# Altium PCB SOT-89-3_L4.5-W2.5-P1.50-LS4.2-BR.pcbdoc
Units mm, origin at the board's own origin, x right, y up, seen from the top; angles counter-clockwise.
Board outline 18.08 x 17.35 mm, 2 copper layers (Top Layer, Bottom Layer), stack 0.07 mm thick; 1 components, 0 nets, 3 pads, 0 vias.
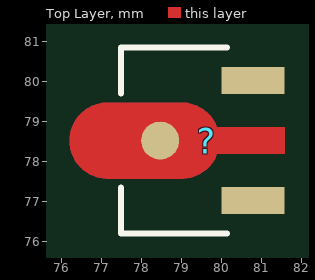
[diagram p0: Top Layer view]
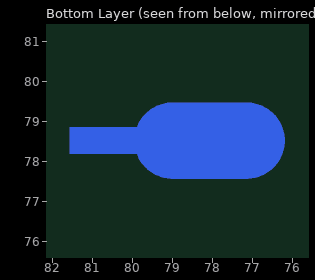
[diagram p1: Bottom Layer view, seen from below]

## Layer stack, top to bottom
Top Solder Mask Layer: solder mask 0.01, Dk 3.3
Top Layer: signal copper 0.035
Bottom Layer: signal copper 0.035
Bottom Solder Mask Layer: solder mask 0.01, Dk 3.3

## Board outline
87.927,69.85 69.85,69.85 69.85,87.202 87.927,87.202

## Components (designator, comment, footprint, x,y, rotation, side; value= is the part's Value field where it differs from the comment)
? "SOT-89-3_L4.5-W2.5-P1.50-LS4.2-BR" SOT-89-3_L4.5-W2.5-P1.50-LS4.2-BR 79.433,78.526 r0 top

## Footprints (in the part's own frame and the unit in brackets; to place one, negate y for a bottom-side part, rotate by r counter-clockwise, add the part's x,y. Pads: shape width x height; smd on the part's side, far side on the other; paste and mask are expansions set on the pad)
SOT-89-3_L4.5-W2.5-P1.50-LS4.2-BR [mm]
  rect 1.575x0.672 smd paste+0 mask+0.051: 1(1.356,-1.5) 3(1.356,1.5)
  round 0.95 smd: 2(-0.966,0)
  Top Layer region: -2.283,0.95 -0.429,0.95 -0.384,0.949 -0.34,0.946 -0.296,0.94 -0.252,0.933 -0.208,0.924 -0.165,0.912 -0.123,0.899 -0.081,0.884 -0.04,0.866 0,0.847 0.04,0.826 0.078,0.803 0.115,0.779 0.151,0.752 0.185,0.724 0.219,0.695 0.251,0.664 0.281,0.631 0.31,0.597 0.337,0.562 0.362,0.525 0.386,0.488 0.408,0.449 0.428,0.409 0.447,0.33 2.144,0.33 2.144,-0.33 0.447,-0.33 0.428,-0.409 0.408,-0.449 0.386,-0.488 0.362,-0.526 0.337,-0.562 0.31,-0.597 0.281,-0.631 0.251,-0.664 0.219,-0.695 0.185,-0.725 0.151,-0.753 0.115,-0.779 0.078,-0.804 0.04,-0.827 0,-0.848 -0.04,-0.867 -0.081,-0.884 -0.123,-0.899 -0.165,-0.913 -0.208,-0.924 -0.252,-0.934 -0.296,-0.941 -0.34,-0.946 -0.384,-0.949 -0.429,-0.95 -2.283,-0.95 -2.328,-0.949 -2.372,-0.946 -2.416,-0.941 -2.46,-0.934 -2.504,-0.924 -2.547,-0.913 -2.589,-0.899 -2.631,-0.884 -2.672,-0.867 -2.713,-0.848 -2.752,-0.827 -2.79,-0.804 -2.827,-0.779 -2.863,-0.753 -2.898,-0.725 -2.931,-0.695 -2.963,-0.664 -2.993,-0.631 -3.022,-0.597 -3.049,-0.562 -3.075,-0.526 -3.098,-0.488 -3.12,-0.449 -3.141,-0.409 -3.159,-0.369 -3.175,-0.327 -3.189,-0.285 -3.202,-0.242 -3.212,-0.199 -3.22,-0.155 -3.227,-0.111 -3.231,-0.067 -3.233,-0.022 -3.233,0.022 -3.231,0.067 -3.227,0.111 -3.22,0.155 -3.212,0.199 -3.202,0.242 -3.189,0.285 -3.175,0.327 -3.159,0.369 -3.141,0.409 -3.12,0.449 -3.098,0.488 -3.075,0.525 -3.049,0.562 -3.022,0.597 -2.993,0.631 -2.963,0.664 -2.931,0.695 -2.898,0.724 -2.863,0.752 -2.827,0.779 -2.79,0.803 -2.752,0.826 -2.713,0.847 -2.672,0.866 -2.631,0.884 -2.589,0.899 -2.547,0.912 -2.504,0.924 -2.46,0.933 -2.416,0.94 -2.372,0.946 -2.328,0.949
  Bottom Layer region: -2.283,0.95 -0.429,0.95 -0.384,0.949 -0.34,0.946 -0.296,0.94 -0.252,0.933 -0.208,0.924 -0.165,0.912 -0.123,0.899 -0.081,0.884 -0.04,0.866 0,0.847 0.04,0.826 0.078,0.803 0.115,0.779 0.151,0.752 0.185,0.724 0.219,0.695 0.251,0.664 0.281,0.631 0.31,0.597 0.337,0.562 0.362,0.525 0.386,0.488 0.408,0.449 0.428,0.409 0.447,0.33 2.144,0.33 2.144,-0.33 0.447,-0.33 0.428,-0.409 0.408,-0.449 0.386,-0.488 0.362,-0.526 0.337,-0.562 0.31,-0.597 0.281,-0.631 0.251,-0.664 0.219,-0.695 0.185,-0.725 0.151,-0.753 0.115,-0.779 0.078,-0.804 0.04,-0.827 0,-0.848 -0.04,-0.867 -0.081,-0.884 -0.123,-0.899 -0.165,-0.913 -0.208,-0.924 -0.252,-0.934 -0.296,-0.941 -0.34,-0.946 -0.384,-0.949 -0.429,-0.95 -2.283,-0.95 -2.328,-0.949 -2.372,-0.946 -2.416,-0.941 -2.46,-0.934 -2.504,-0.924 -2.547,-0.913 -2.589,-0.899 -2.631,-0.884 -2.672,-0.867 -2.713,-0.848 -2.752,-0.827 -2.79,-0.804 -2.827,-0.779 -2.863,-0.753 -2.898,-0.725 -2.931,-0.695 -2.963,-0.664 -2.993,-0.631 -3.022,-0.597 -3.049,-0.562 -3.075,-0.526 -3.098,-0.488 -3.12,-0.449 -3.141,-0.409 -3.159,-0.369 -3.175,-0.327 -3.189,-0.285 -3.202,-0.242 -3.212,-0.199 -3.22,-0.155 -3.227,-0.111 -3.231,-0.067 -3.233,-0.022 -3.233,0.022 -3.231,0.067 -3.227,0.111 -3.22,0.155 -3.212,0.199 -3.202,0.242 -3.189,0.285 -3.175,0.327 -3.159,0.369 -3.141,0.409 -3.12,0.449 -3.098,0.488 -3.075,0.525 -3.049,0.562 -3.022,0.597 -2.993,0.631 -2.963,0.664 -2.931,0.695 -2.898,0.724 -2.863,0.752 -2.827,0.779 -2.79,0.803 -2.752,0.826 -2.713,0.847 -2.672,0.866 -2.631,0.884 -2.589,0.899 -2.547,0.912 -2.504,0.924 -2.46,0.933 -2.416,0.94 -2.372,0.946 -2.328,0.949
  Multi-Layer region: -2.283,0.95 -0.429,0.95 -0.384,0.949 -0.34,0.946 -0.296,0.94 -0.252,0.933 -0.208,0.924 -0.165,0.912 -0.123,0.899 -0.081,0.884 -0.04,0.866 0,0.847 0.04,0.826 0.078,0.803 0.115,0.779 0.151,0.752 0.185,0.724 0.219,0.695 0.251,0.664 0.281,0.631 0.31,0.597 0.337,0.562 0.362,0.525 0.386,0.488 0.408,0.449 0.428,0.409 0.447,0.33 2.144,0.33 2.144,-0.33 0.447,-0.33 0.428,-0.409 0.408,-0.449 0.386,-0.488 0.362,-0.526 0.337,-0.562 0.31,-0.597 0.281,-0.631 0.251,-0.664 0.219,-0.695 0.185,-0.725 0.151,-0.753 0.115,-0.779 0.078,-0.804 0.04,-0.827 0,-0.848 -0.04,-0.867 -0.081,-0.884 -0.123,-0.899 -0.165,-0.913 -0.208,-0.924 -0.252,-0.934 -0.296,-0.941 -0.34,-0.946 -0.384,-0.949 -0.429,-0.95 -2.283,-0.95 -2.328,-0.949 -2.372,-0.946 -2.416,-0.941 -2.46,-0.934 -2.504,-0.924 -2.547,-0.913 -2.589,-0.899 -2.631,-0.884 -2.672,-0.867 -2.713,-0.848 -2.752,-0.827 -2.79,-0.804 -2.827,-0.779 -2.863,-0.753 -2.898,-0.725 -2.931,-0.695 -2.963,-0.664 -2.993,-0.631 -3.022,-0.597 -3.049,-0.562 -3.075,-0.526 -3.098,-0.488 -3.12,-0.449 -3.141,-0.409 -3.159,-0.369 -3.175,-0.327 -3.189,-0.285 -3.202,-0.242 -3.212,-0.199 -3.22,-0.155 -3.227,-0.111 -3.231,-0.067 -3.233,-0.022 -3.233,0.022 -3.231,0.067 -3.227,0.111 -3.22,0.155 -3.212,0.199 -3.202,0.242 -3.189,0.285 -3.175,0.327 -3.159,0.369 -3.141,0.409 -3.12,0.449 -3.098,0.488 -3.075,0.525 -3.049,0.562 -3.022,0.597 -2.993,0.631 -2.963,0.664 -2.931,0.695 -2.898,0.724 -2.863,0.752 -2.827,0.779 -2.79,0.803 -2.752,0.826 -2.713,0.847 -2.672,0.866 -2.631,0.884 -2.589,0.899 -2.547,0.912 -2.504,0.924 -2.46,0.933 -2.416,0.94 -2.372,0.946 -2.328,0.949
  silkscreen extent -1.95,-2.33 0.7,2.33

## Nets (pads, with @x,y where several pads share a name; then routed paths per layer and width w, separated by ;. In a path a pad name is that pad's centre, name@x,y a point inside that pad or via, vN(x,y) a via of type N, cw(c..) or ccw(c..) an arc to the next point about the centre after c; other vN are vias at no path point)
pads on no net: ?.1 ?.2 ?.3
